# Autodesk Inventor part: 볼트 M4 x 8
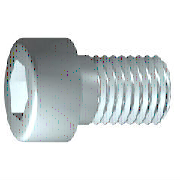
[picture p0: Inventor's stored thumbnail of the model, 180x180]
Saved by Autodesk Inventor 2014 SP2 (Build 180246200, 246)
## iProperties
IsCustomPart: 0
Created: 2012-02
Part Number: 볼트 M4 x 8
Material: 스테인리스강
Description: 6각 소켓 머리 캡 나사
Document SubType Name: Modeling
Standard: ISO 4762
Designer: mduedu
Standard Revision: Fourth edition 2004-03-01
Standards Organization: ISO
Language: ko-KR
Size Designation: M4 x 8
Categories: <MemberInstance><Categories><Category DisplayName="조임쇠" InternalName="e4da775c-781d-43d5-af7c-5136215cf5a6" Mnemonic="FSTN"><Category DisplayName="볼트" InternalN
Density: 8.08 g/cm^3
Appearance: 반광택
Mass: 1.89105 g
Surface Area: 2.80587 cm^2
Volume: 0.234041 cm^3
Author: mduedu
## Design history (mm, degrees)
sketch "스케치1"
  geometry: L1 (-1, 0)-(8, 0); L2 (8, 0)-(8, 2); L3 (8, 2)-(1.75, 2); L4 (1.75, 2)-(1.32, 2); L5 (1.32, 2)-(0, 2); L6 (0, 2)-(0, 3.5); L7 (0, 3.5)-(-4, 3.5); L8 (-4, 3.5)-(-4, 1.732); L9 (-4, 1.732)-(-2, 1.732); L10 (-2, 1.732)-(-1, 0); L11 (-6.4, 0)-(10.4, 0) reference; L12 (0, -0.7)-(0, 4.2) reference; L13 (1.75, 2)-(0, 2)
  constraints: 22 end point, 6 parallel, 2 collinear, 2 perpendicular, 1 horizontal, 1 point on line
  dimensions: "d1" = 6.25 distance from line of L3.end L2 (= GEL); "d2" = 0.42952 distance of L4.end L3.end (computed from GAL); "d3" = 4 distance between parallel lines of L8 L6 (= KOH); "d4" = 2 distance of L8.end L9.end (= INTI); "d5" = 60 deg angle of L10 L1; "d6" = 4 diameter of L3 L1 (= GD); "d7" = 4 diameter of L5 L1 (= BDM); "d8" = 3.4641 diameter of L9 L1 (= 1.1547 x SW); "d9" = 7 diameter of L7 L1 (= KOD); "d26" = 8 distance between parallel lines of L12 L2 (= NLG)
revolve "본체" sketch "스케치1" stored, may be unused: angle "d10" = 90 deg
sketch "스케치2"
  geometry: L1 (0, -4.9)-(0, 4.9) reference; L2 (-4.9, 0)-(4.9, 0) reference; L3 (1.732, 0)-(0.866, -1.5); L4 (0.866, -1.5)-(-0.866, -1.5); L5 (-0.866, -1.5)-(-1.732, 0); L6 (-1.732, 0)-(-0.866, 1.5); L7 (-0.866, 1.5)-(0.866, 1.5); L8 (0.866, 1.5)-(1.732, 0); 2 further points
  constraints: 12 end point, 1 coincident, 1 horizontal alignment, 1 point on line, 12 other
extrude "슬롯" join sketch "스케치2" stored distance "d11" = 10; taper "d12" = 0 deg
workplane "Work Plane1"
fillet "Fillet2" dims "d30" = 0.1 (= R)
body "Solid1"
fillet "모깎기1" dims "d17" = 0.4 (= RR)
feature "스레드" dims "d13" = 6.25 (= GEL), "d14" = 0
chamfer "모따기1" distance "d15" = 0.42941 (= -0.5 x SPD + 0.5 x GD); stored, may be unused: second distance "d16" = 0.42941 (= GUL), angle "d27" = 45 deg
other parameters: "GD" = 4 [user parameter; used in 2 equation terms], "NLG" = 8 [user parameter; used in 1 equation term], "GEL" = 6.25 [user parameter; used in 2 equation terms], "KOD" = 7 [user parameter; used in 1 equation term], "KOH" = 4 [user parameter; used in 1 equation term], "INTI" = 2 [user parameter; used in 1 equation term], "GAL" = 0.42941 (= 0.61345 x PTC) [user parameter; used in 1 equation term], "GUL" = 0.42941 (= 0.61345 x PTC) [user parameter; used in 1 equation term], "BDM" = 4 (= NND) [user parameter; used in 1 equation term], "SW" = 3 [user parameter; used in 2 equation terms], "RR" = 0.4 [user parameter; used in 1 equation term], "SPD" = 3.14117 (= NND - 1.2269 x PTC) [user parameter; used in 1 equation term], "d19" = 0, "d28" = 0, "d29" = 0, "R" = 0.1 [user parameter; used in 1 equation term], "TOA" = 30 deg [user parameter], "GD1" = 3.14117 (= THREADDIA - 1.2269 x PTC) [user parameter], "THREADDIA" = 4 [user parameter; used in 1 equation term], "FAWI" = 45 deg [user parameter], "TPU" = 14.28571 (computed from PTC) [user parameter], "PTC" = 0.7 [user parameter; used in 5 equation terms], "NND" = 4 [user parameter; used in 2 equation terms], "E0" = 3.465 (= 1.155 x SW) [user parameter]
